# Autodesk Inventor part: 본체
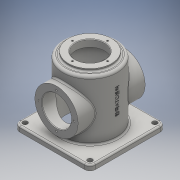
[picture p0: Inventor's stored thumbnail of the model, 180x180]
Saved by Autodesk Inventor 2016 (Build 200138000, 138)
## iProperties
Created: 2019-08
Part Number: 본체
Material: 일반
Document SubType Name: Modeling
Designer: user
Density: 1 g/cm^3
Appearance: 기본값
Author: user
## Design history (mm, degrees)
sketch "스케치1"
  geometry: L1 (-70, -70)-(70, -70); L2 (70, -70)-(70, 70); L3 (70, 70)-(-70, 70); L4 (-70, 70)-(-70, -70); L5 (-70, -70)-(70, 70); L6 (70, -70)-(-70, 70); 1 further point
  constraints: 12 end point, 2 midpoint, 2 parallel, 1 horizontal, 1 perpendicular
  dimensions: "d0" = 140 distance of L3.end L2.end; "d1" = 140 distance of L2.end L1.end
extrude "돌출1" new body sketch "스케치1" distance "d2" = 10; taper "d3" = 0 deg
sketch "스케치2"
  geometry: C1 r 50 at (0, 0); 1 further point
  constraints: 1 centre point, 1 coincident
  dimensions: "d4" = 100 diameter of C1
extrude "돌출2" join sketch "스케치2" distance "d5" = 110; taper "d6" = 0 deg
node "작업 평면1"
sketch "스케치3"
  geometry: C1 r 40 at (0, 0); 1 further point
  constraints: 1 centre point, 1 coincident
  dimensions: "d8" = 80 diameter of C1
extrude "돌출3" join sketch "스케치3" stored distance "d9" = 110; taper "d10" = 0 deg
sketch "스케치5" dims "d27" = 65
  geometry: 3 further points
  constraints: 2 horizontal alignment, 1 coincident, 2 other
hole "구멍3" sketch "스케치5" at (-32.5, 0) diameter "d28" = 3.242; stored, may be unused: countersink angle "d32" = 90 deg, drill point angle "d34" = 118 deg; dims "d29" = 8, "d30" = 4, "d31" = 2, "d33" = 10
node "작업 평면2"
sketch "스케치6"
  geometry: L1 (140, 0)-(0, 0) reference; L2 (0, 0)-(0, 10) reference; L3 (0, 10)-(140, 10) reference; L4 (140, 10)-(140, 0) reference; L5 (140, 0)-(0, 0) reference; L6 (0, 0)-(0, 10) reference; L7 (0, 10)-(140, 10) reference; L8 (140, 10)-(140, 0) reference; C1 r 40 at (70, 60); 1 further point
  constraints: 1 centre point
  dimensions: "d39" = 80 diameter of C1; "d40" = 60 distance from line of L1 C1.centre; "d41" = 70 distance from line of C1.centre L4
extrude "돌출4" join sketch "스케치6" distance "d42" = 124; taper "d43" = 0 deg
sketch "스케치7"
  geometry: 2 further points
  constraints: 1 coincident
hole "구멍4" sketch "스케치7" at (0, 0) diameter "d44" = 90; stored, may be unused: countersink angle "d48" = 90 deg, drill point angle "d50" = 0 deg; dims "d45" = 6, "d46" = 4, "d47" = 2, "d49" = 112
hole "구멍5" diameter "d53" = 54; stored, may be unused: countersink angle "d57" = 90 deg, drill point angle "d59" = 0 deg; dims "d51" = 10, "d52" = 10, "d54" = 6, "d55" = 4, "d56" = 2, "d58" = 13
hole "구멍6" diameter "d62" = 54; stored, may be unused: countersink angle "d66" = 90 deg, drill point angle "d68" = 0 deg; dims "d60" = 10, "d61" = 10, "d63" = 6, "d64" = 4, "d65" = 2, "d67" = 13
sketch "스케치8" dims "d69" = 65
  geometry: L1 (70, -60)-(-70, -60) reference; L2 (-70, -60)-(-70, -50) reference; L3 (-70, -50)-(70, -50) reference; L4 (70, -50)-(70, -60) reference; C1 r 27 at (0, 0) reference; C2 r 40 at (0, 0) reference; 3 further points
  constraints: 2 vertical alignment, 1 coincident, 2 other
hole "구멍7" sketch "스케치8" at (0, 32.5) diameter "d70" = 3.242; stored, may be unused: countersink angle "d74" = 90 deg, drill point angle "d76" = 118 deg; dims "d71" = 8, "d72" = 4, "d73" = 2, "d75" = 10
fillet "모깎기1" dims "d80" = 10
hole "구멍8" diameter "d83" = 9; stored, may be unused: countersink angle "d87" = 90 deg, drill point angle "d89" = 0 deg; dims "d81" = 10, "d82" = 10, "d84" = 8, "d85" = 4, "d86" = 2, "d88" = 10
hole "구멍9" diameter "d92" = 9; stored, may be unused: countersink angle "d96" = 90 deg, drill point angle "d98" = 0 deg; dims "d90" = 10, "d91" = 10, "d93" = 8, "d94" = 4, "d95" = 2, "d97" = 10
hole "구멍10" diameter "d101" = 9; stored, may be unused: countersink angle "d105" = 90 deg, drill point angle "d107" = 0 deg; dims "d99" = 10, "d100" = 10, "d102" = 8, "d103" = 4, "d104" = 2, "d106" = 10
hole "구멍11" diameter "d110" = 9; stored, may be unused: countersink angle "d114" = 90 deg, drill point angle "d116" = 0 deg; dims "d108" = 10, "d109" = 10, "d111" = 8, "d112" = 4, "d113" = 2, "d115" = 10
chamfer "모따기1" distance "d117" = 1; stored, may be unused: second distance "d118" = 2, angle "d119" = 45 deg
fillet "모깎기2" dims "d120" = 3
fillet "모깎기3" dims "d121" = 3
fillet "모깎기4" dims "d122" = 3
fillet "모깎기5" dims "d123" = 5
node "작업 평면3"
sketch "스케치9"
  geometry: 2 further points
  constraints: 1 horizontal alignment, 1 other
  dimensions: "d125" = 70 distance of point (0, 60) point (-70, 60)
feature "엠보싱1" sketch "스케치9" dims "d0" = 140, "d1" = 140, "d126" = 0.5, "d127" = 0
node "솔리드1"
pattern_circular "원형 패턴1" dims angle "d36" = 360 deg
pattern_circular "원형 패턴2" dims angle "d78" = 360 deg
mirror "대칭1"
node "절단 모서리 투영1"
node "절단 모서리 투영2"
node "절단 모서리 투영3"
other parameters: "d7" = -125, "d38" = -8, "d124" = 3.25
